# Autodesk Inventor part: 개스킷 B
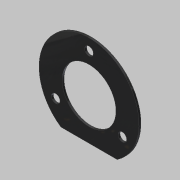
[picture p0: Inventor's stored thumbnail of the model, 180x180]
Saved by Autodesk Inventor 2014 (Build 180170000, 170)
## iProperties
Created: 2020-04
Part Number: 개스킷 B
Material: 고무
Document SubType Name: Modeling
Designer: mduedu
Density: 1 g/cm^3
Appearance: 고무 - 검은색 - 버전 1.1
Author: mduedu
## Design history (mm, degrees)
sketch "스케치1"
  geometry: C1 r 26 at (0, 0); 1 further point
  constraints: 1 centre point, 1 coincident
  dimensions: "d0" = 52 diameter of C1
extrude "돌출1" new body sketch "스케치1" distance "d1" = 1; taper "d2" = 0 deg
sketch "스케치2"
  geometry: L1 (-14.62, -21.5)-(14.62, -21.5); A1 r 26 centre (0, 0) between (-14.62, -21.5) and (14.62, -21.5) reference; 1 further point
  constraints: 2 end point, 2 point on circle, 1 horizontal
  dimensions: "d3" = 21.5 distance from line of L1 point (0, 0)
extrude "돌출2" cut sketch "스케치2" stored distance "d4" = 1; taper "d5" = 0 deg
sketch "스케치3" dims "d6" = 40
  geometry: 3 further points
  constraints: 2 vertical alignment, 1 coincident, 2 other
hole "구멍1" sketch "스케치3" at (0, 20) diameter "d7" = 4.5; stored, may be unused: countersink angle "d11" = 90 deg, drill point angle "d13" = 118 deg; dims "d8" = 6, "d9" = 4, "d10" = 2, "d12" = 8
sketch "스케치4"
  geometry: C1 r 14 at (0, 0); 1 further point
  constraints: 1 centre point, 1 coincident
  dimensions: "d17" = 28 diameter of C1
extrude "돌출3" cut sketch "스케치4" stored distance "d18" = 1; taper "d19" = 0 deg
node "솔리드1"
pattern_circular "원형 패턴1" dims angle "d15" = 360 deg
node "투영된 루프1"
